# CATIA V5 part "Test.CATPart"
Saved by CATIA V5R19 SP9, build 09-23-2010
Part number: Part2
Bounding box of the stored display mesh (mm): x 0 to 262, y -65.305 to 74.6, z 0 to 0
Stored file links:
  C:\Users\schwarz_maximilian\Desktop\Test.CATPart
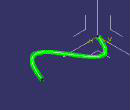
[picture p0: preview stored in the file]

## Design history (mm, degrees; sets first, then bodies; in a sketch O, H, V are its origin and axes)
AxisSystem1: origin (0, 0, 0), X (1, 0, 0), Y (0, 1, 0), Z (0, 0, 1)
Set1
  Sketch1 on XY plane of AxisSystem1, origin (0, 0, 0), H (1, 0, 0), V (0, 1, 0)
    spline S1 through (0, 0) (60, 74) (167, -58) (262, 36)
    point P1 (0, 0)
    coincidence: P1 O
  CLDGeom1 "Kurven diskretisieren.1"
  CLDGeom2 "Punkte_Kurven diskretisieren.1_1_Kurven diskretisieren.1_1.2"
Body1 (main body)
